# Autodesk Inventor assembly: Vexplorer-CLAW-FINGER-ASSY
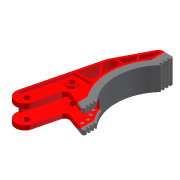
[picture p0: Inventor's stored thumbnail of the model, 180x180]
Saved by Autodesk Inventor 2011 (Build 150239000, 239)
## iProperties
Created: 2007-10
Part Number: Vexplorer-CLAW-FINGER-ASSY
Document SubType Name: Assembly
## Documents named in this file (3)
- C:\Data Folder\VEX 2011\Inventor Datasets\Unit 12\Components\Vexplorer-CLAW-FINGER-ASSY.iam
- C:\Data Folder\VEX 2011\Inventor Datasets\Unit 12\Components\Vexplorer-CLAW-FINGER.ipt
- C:\Data Folder\VEX 2011\Inventor Datasets\Unit 12\Components\Vexplorer-CLAW-FINGER-RUBBER.ipt
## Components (2 placed, 2 different names)
1. Vexplorer-CLAW-FINGER — Angle:1
2. Vexplorer-CLAW-FINGER-RUBBER — Mate:1
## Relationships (2: Mate 1, Angle 1)
- Mate:1: Vexplorer-CLAW-FINGER-RUBBER
- Angle:1: Vexplorer-CLAW-FINGER
